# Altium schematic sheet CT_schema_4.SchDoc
size 298 x 247 mm
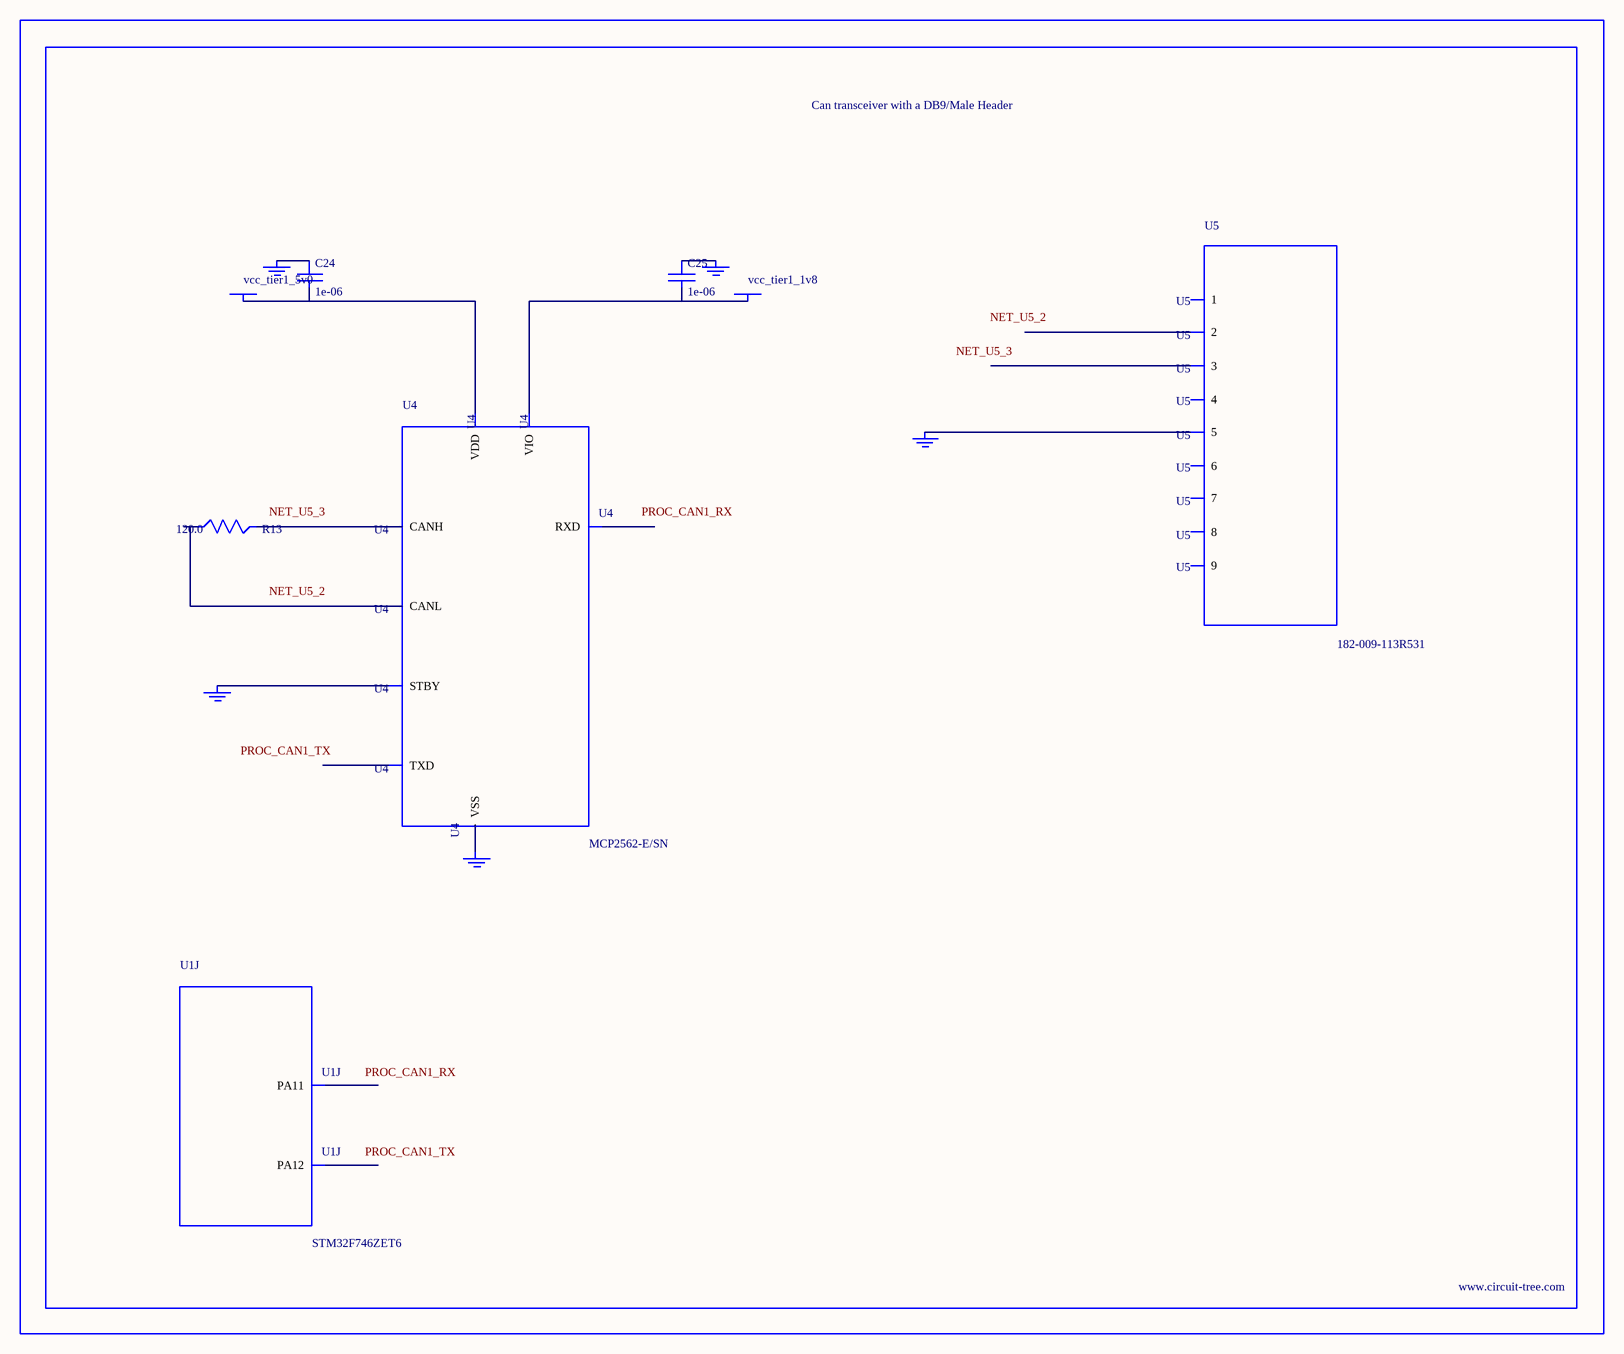
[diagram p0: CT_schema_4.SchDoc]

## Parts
BORDER3  (no value)
C24  1e-06  [C0603]
C25  1e-06  [C0603]
GND_INSTANCE_3_0  (no value)
GND_INSTANCE_3_1  (no value)
GND_INSTANCE_3_2  (no value)
GND_INSTANCE_3_3  (no value)
GND_INSTANCE_3_4  (no value)
POWER_INSTANCE_3_0  vcc_tier1_5v0
POWER_INSTANCE_3_1  vcc_tier1_1v8
R13  120.0  [R0603]
U1  STM32F746ZET6  [LQFP144]  (part J of 13)
U4  MCP2562-E/SN  [SOIC-8]
U5  182-009-113R531  [182-009-MALE]

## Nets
NetC24_1: C24.1 GND_INSTANCE_3_0.0(GND)
NetC24_2: C24.2 POWER_INSTANCE_3_0.0(PWR) U4.3(VDD)
NetC25_1: C25.1 GND_INSTANCE_3_1.0(GND)
NetC25_2: C25.2 POWER_INSTANCE_3_1.0(PWR) U4.5(VIO)
NetGND_INSTANCE_3_2_0: GND_INSTANCE_3_2.0(GND) U4.8(STBY)
NetGND_INSTANCE_3_3_0: GND_INSTANCE_3_3.0(GND) U4.2(VSS)
NetGND_INSTANCE_3_4_0: GND_INSTANCE_3_4.0(GND) U5.5
NetR13_1: R13.1 U4.6(CANL)
NetR13_2: R13.2 U4.7(CANH)

Not connected (* = marked no-connect by the designer): U1 103(PA11) 104(PA12); U4 1(TXD) 4(RXD); U5 1 2 3 4 6 7 8 9

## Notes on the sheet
- Labels drawn without touching a wire or pin: NET_U5_2, NET_U5_3, PROC_CAN1_RX, PROC_CAN1_TX

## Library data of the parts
BORDER3 = BORDER_PAGE3
C24 C25 = C0603C105K3RACTU
GND_INSTANCE_3_0-GND_INSTANCE_3_4 = GND
POWER_INSTANCE_3_0 POWER_INSTANCE_3_1 = PWR
R13 = RC0603JR-07120RL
